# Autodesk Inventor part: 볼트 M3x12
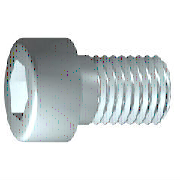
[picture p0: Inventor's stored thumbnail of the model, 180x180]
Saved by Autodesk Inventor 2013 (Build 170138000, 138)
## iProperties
IsCustomPart: 0
Created: 2012-02
Part Number: 볼트 M3x12
Material: 강철, 연강
Description: 6각머리 태핑 나사
Document SubType Name: Modeling
Standard: KS B 1003
Designer: mduedu
Standards Organization: KS
Language: ko-KR
Size Designation: M 3 x 12
Categories: <MemberInstance><Categories><Category DisplayName="조임쇠" InternalName="e4da775c-781d-43d5-af7c-5136215cf5a6" Mnemonic="FSTN"><Category DisplayName="볼트" InternalN
Density: 7.86 g/cm^3
Mass: 1.15208 g
Surface Area: 2.207 cm^2
Volume: 0.146575 cm^3
Author: mduedu
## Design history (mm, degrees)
sketch "스케치1"
  geometry: L1 (-0.867, 0)-(12, 0); L2 (12, 0)-(12, 1.5); L3 (12, 1.5)-(1.25, 1.5); L4 (1.25, 1.5)-(0.943, 1.5); L5 (0.943, 1.5)-(0, 1.5); L6 (0, 1.5)-(0, 2.75); L7 (0, 2.75)-(-3, 2.75); L8 (-3, 2.75)-(-3, 1.443); L9 (-3, 1.443)-(-1.7, 1.443); L10 (-1.7, 1.443)-(-0.867, 0); L11 (-6, 0)-(15, 0) reference; L12 (0, -0.55)-(0, 3.3) reference; L13 (1.25, 1.5)-(0, 1.5)
  constraints: 22 end point, 6 parallel, 2 collinear, 2 perpendicular, 1 horizontal, 1 point on line
  dimensions: "d1" = 10.75 distance from line of L3.end L2 (= GEL); "d2" = 0.30683 distance of L4.end L3.end (computed from GAL); "d3" = 3 distance between parallel lines of L8 L6 (= KOH); "d4" = 1.3 distance of L8.end L9.end (= INTI); "d5" = 60 deg angle of L10 L1; "d6" = 3 diameter of L3 L1 (= GD); "d7" = 3 diameter of L5 L1 (= BDM); "d8" = 2.88675 diameter of L9 L1 (= 1.1547 x SW); "d9" = 5.5 diameter of L7 L1 (= KOD); "d26" = 12 distance between parallel lines of L12 L2 (= NLG)
revolve "본체" sketch "스케치1" stored, may be unused: angle "d10" = 90 deg
sketch "스케치2"
  geometry: L1 (0, -3.85)-(0, 3.85) reference; L2 (-3.85, 0)-(3.85, 0) reference; L3 (1.443, 0)-(0.722, -1.25); L4 (0.722, -1.25)-(-0.722, -1.25); L5 (-0.722, -1.25)-(-1.443, 0); L6 (-1.443, 0)-(-0.722, 1.25); L7 (-0.722, 1.25)-(0.722, 1.25); L8 (0.722, 1.25)-(1.443, 0); 2 further points
  constraints: 12 end point, 1 coincident, 1 horizontal alignment, 1 point on line, 12 other
extrude "슬롯" join sketch "스케치2" stored distance "d11" = 10; taper "d12" = 0 deg
workplane "Work Plane1"
fillet "Fillet2" dims "d30" = 0.1 (= R)
body "Solid1"
fillet "모깎기1" dims "d17" = 0.3 (= RR)
feature "스레드" dims "d13" = 10.75 (= GEL), "d14" = 0
chamfer "모따기1" distance "d15" = 0.30673 (= -0.5 x SPD + 0.5 x GD); stored, may be unused: second distance "d16" = 0.30673 (= GUL), angle "d27" = 45 deg
other parameters: "GD" = 3 (= NND) [user parameter; used in 2 equation terms], "NLG" = 12 [user parameter; used in 1 equation term], "GEL" = 10.75 [user parameter; used in 2 equation terms], "KOD" = 5.5 [user parameter; used in 1 equation term], "KOH" = 3 [user parameter; used in 1 equation term], "INTI" = 1.3 [user parameter; used in 1 equation term], "GAL" = 0.30673 (= 0.61345 x PTC) [user parameter; used in 1 equation term], "GUL" = 0.30673 (= 0.61345 x PTC) [user parameter; used in 1 equation term], "BDM" = 3 (= NND) [user parameter; used in 1 equation term], "SW" = 2.5 [user parameter; used in 2 equation terms], "RR" = 0.3 [user parameter; used in 1 equation term], "SPD" = 2.38655 (= NND - 1.2269 x PTC) [user parameter; used in 1 equation term], "d19" = 0, "d28" = 0, "d29" = 0, "R" = 0.1 [user parameter; used in 1 equation term], "PHH" = 0.1 [user parameter], "GD1" = 2.38655 (= THREADDIA - 1.2269 x PTC) [user parameter], "THREADDIA" = 3 [user parameter; used in 1 equation term], "FAWI" = 45 deg [user parameter], "PTC" = 0.5 [user parameter; used in 5 equation terms], "NND" = 3 [user parameter; used in 3 equation terms], "TOA" = 30 deg [user parameter], "E0" = 2.8875 (= 1.155 x SW) [user parameter]
